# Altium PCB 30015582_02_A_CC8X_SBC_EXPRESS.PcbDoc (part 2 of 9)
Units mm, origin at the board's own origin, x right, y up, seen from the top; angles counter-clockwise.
Board outline 87 x 63 mm, 6 copper layers (Top Layer-L1, GND Plane-L2, Signal-L3, PWR/Signal-L4, GND Plane-L5, Bottom Layer-L6), stack 1.172 mm thick; 169 components, 171 nets, 693 pads, 391 vias.
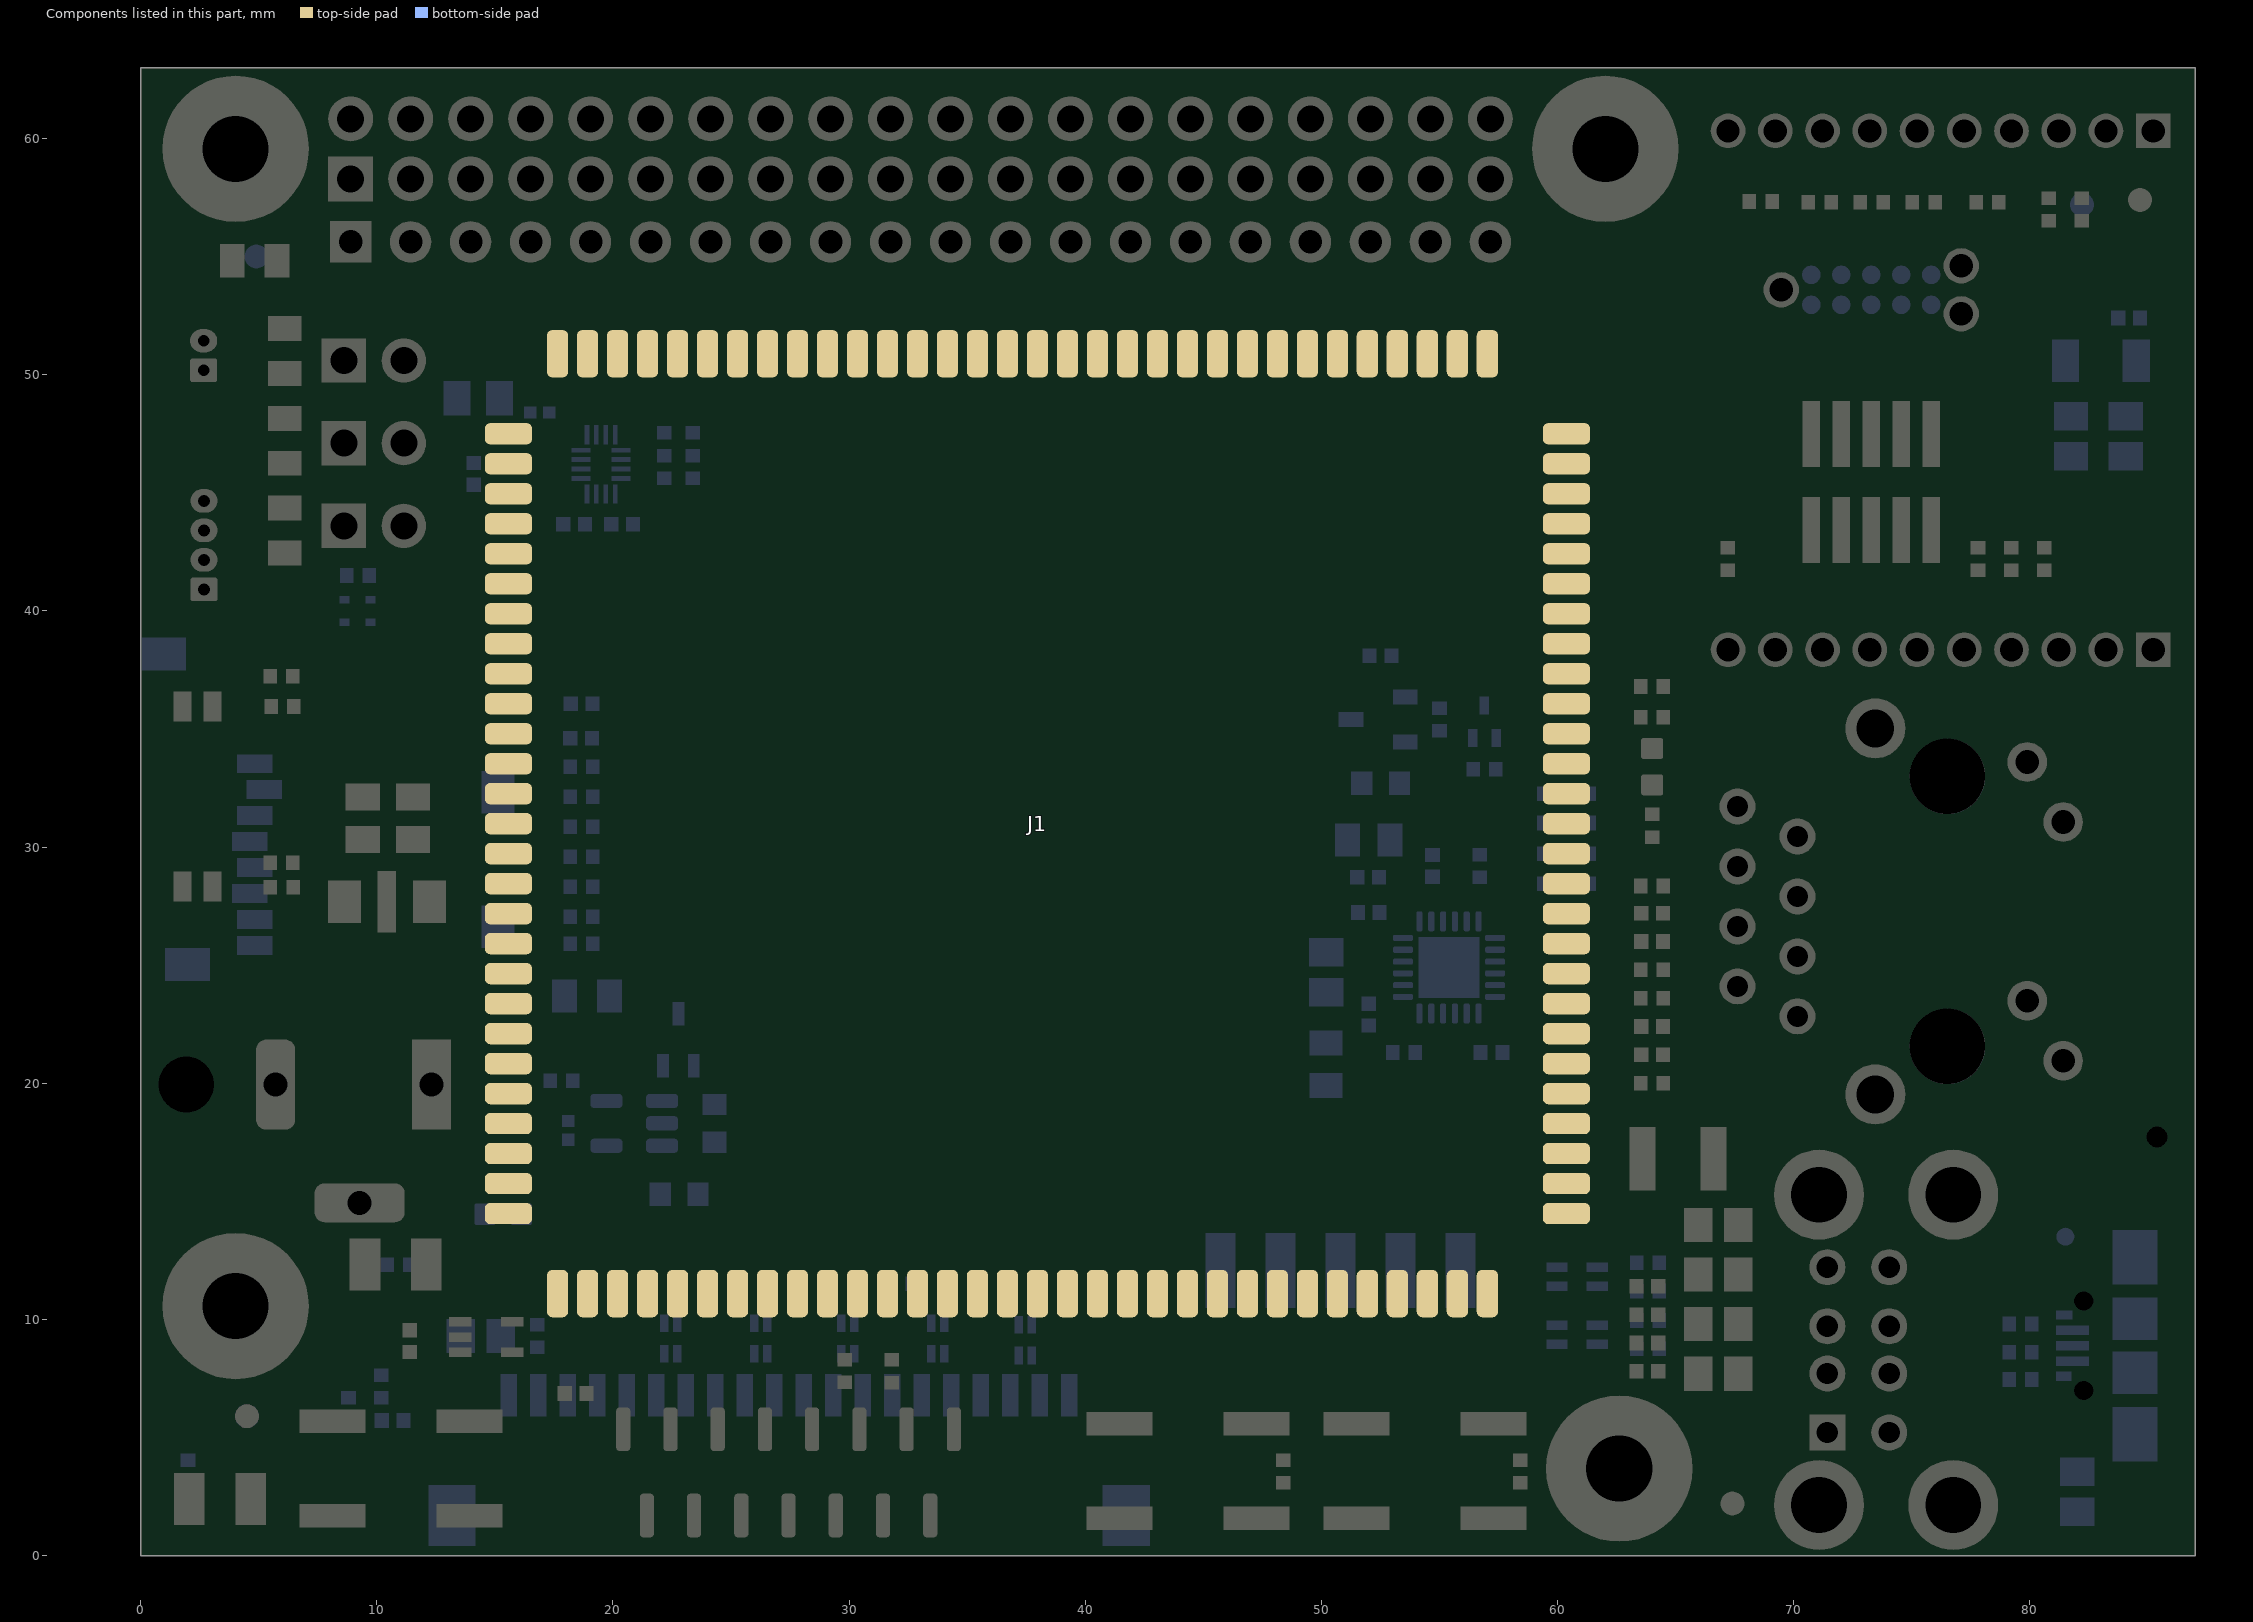
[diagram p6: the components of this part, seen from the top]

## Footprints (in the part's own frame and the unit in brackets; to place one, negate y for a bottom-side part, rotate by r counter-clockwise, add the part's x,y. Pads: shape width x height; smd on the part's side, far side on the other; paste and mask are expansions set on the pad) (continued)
CC8X_CASTELLATED [mm]
  rrect50% 2x0.9 smd: 1(-19.9,19.05) 2(-19.9,17.78) 3(-19.9,16.51) 4(-19.9,15.24) 5(-19.9,13.97) 6(-19.9,12.7) 7(-19.9,11.43) 8(-19.9,10.16) 9(-19.9,8.89) 10(-19.9,7.62) 11(-19.9,6.35) 12(-19.9,5.08) 13(-19.9,3.81) 14(-19.9,2.54) 15(-19.9,1.27) 16(-19.9,0) 17(-19.9,-1.27) 18(-19.9,-2.54) 19(-19.9,-3.81) 20(-19.9,-5.08) 21(-19.9,-6.35) 22(-19.9,-7.62) 23(-19.9,-8.89) 24(-19.9,-10.16) 25(-19.9,-11.43) 26(-19.9,-12.7) 27(-19.9,-13.97) 28(-19.9,-15.24) 29(-19.9,-16.51) 30(-19.9,-17.78) 31(-19.9,-19.05) 32(-19.9,-20.32) 60(19.9,-20.32) 61(19.9,-19.05) 62(19.9,-17.78) 63(19.9,-16.51) 64(19.9,-15.24) 65(19.9,-13.97) 66(19.9,-12.7) 67(19.9,-11.43) 68(19.9,-10.16) 69(19.9,-8.89) 70(19.9,-7.62) 71(19.9,-6.35) 72(19.9,-5.08) 73(19.9,-3.81) 74(19.9,-2.54) 75(19.9,-1.27) 76(19.9,0) 77(19.9,1.27) 78(19.9,2.54) 79(19.9,3.81) 80(19.9,5.08) 81(19.9,6.35) 82(19.9,7.62) 83(19.9,8.89) 84(19.9,10.16) 85(19.9,11.43) 86(19.9,12.7) 87(19.9,13.97) 88(19.9,15.24) 89(19.9,16.51) 90(19.9,17.78) 91(19.9,19.05)
  rrect50% 0.9x2 smd: 33(-16.51,-22.4) 34(-15.24,-22.4) 35(-13.97,-22.4) 36(-12.7,-22.4) 37(-11.43,-22.4) 38(-10.16,-22.4) 39(-8.89,-22.4) 40(-7.62,-22.4) 41(-6.35,-22.4) 42(-5.08,-22.4) 43(-3.81,-22.4) 44(-2.54,-22.4) 45(-1.27,-22.4) 46(0,-22.4) 47(1.27,-22.4) 48(2.54,-22.4) 49(3.81,-22.4) 50(5.08,-22.4) 51(6.35,-22.4) 52(7.62,-22.4) 53(8.89,-22.4) 54(10.16,-22.4) 55(11.43,-22.4) 56(12.7,-22.4) 57(13.97,-22.4) 58(15.24,-22.4) 59(16.51,-22.4) 92(16.51,22.4) 93(15.24,22.4) 94(13.97,22.4) 95(12.7,22.4) 96(11.43,22.4) 97(10.16,22.4) 98(8.89,22.4) 99(7.62,22.4) 100(6.35,22.4) 101(5.08,22.4) 102(3.81,22.4) 103(2.54,22.4) 104(1.27,22.4) 105(0,22.4) 106(-1.27,22.4) 107(-2.54,22.4) 108(-3.81,22.4) 109(-5.08,22.4) 110(-6.35,22.4) 111(-7.62,22.4) 112(-8.89,22.4) 113(-10.16,22.4) 114(-11.43,22.4) 115(-12.7,22.4) 116(-13.97,22.4) 117(-15.24,22.4) 118(-16.51,22.4)
  Top Layer-L1 keep-out region: -17.58,-10.16 -17.595,-10.237 -17.639,-10.301 -17.703,-10.345 -17.78,-10.36 -17.78,-10.36 -17.857,-10.345 -17.921,-10.301 -17.965,-10.237 -17.98,-10.16 -17.98,-10.16 -17.965,-10.083 -17.921,-10.019 -17.857,-9.975 -17.78,-9.96 -17.78,-9.96 -17.703,-9.975 -17.639,-10.019 -17.595,-10.083 -17.58,-10.16
  Top Layer-L1 keep-out region: -17.58,-8.89 -17.595,-8.967 -17.639,-9.031 -17.703,-9.075 -17.78,-9.09 -17.78,-9.09 -17.857,-9.075 -17.921,-9.031 -17.965,-8.967 -17.98,-8.89 -17.98,-8.89 -17.965,-8.813 -17.921,-8.749 -17.857,-8.705 -17.78,-8.69 -17.78,-8.69 -17.703,-8.705 -17.639,-8.749 -17.595,-8.813 -17.58,-8.89
  Top Layer-L1 keep-out region: -17.58,-7.62 -17.595,-7.697 -17.639,-7.761 -17.703,-7.805 -17.78,-7.82 -17.78,-7.82 -17.857,-7.805 -17.921,-7.761 -17.965,-7.697 -17.98,-7.62 -17.98,-7.62 -17.965,-7.543 -17.921,-7.479 -17.857,-7.435 -17.78,-7.42 -17.78,-7.42 -17.703,-7.435 -17.639,-7.479 -17.595,-7.543 -17.58,-7.62
  Top Layer-L1 keep-out region: -17.58,-6.35 -17.595,-6.427 -17.639,-6.491 -17.703,-6.535 -17.78,-6.55 -17.78,-6.55 -17.857,-6.535 -17.921,-6.491 -17.965,-6.427 -17.98,-6.35 -17.98,-6.35 -17.965,-6.273 -17.921,-6.209 -17.857,-6.165 -17.78,-6.15 -17.78,-6.15 -17.703,-6.165 -17.639,-6.209 -17.595,-6.273 -17.58,-6.35
  Top Layer-L1 keep-out region: -17.58,-5.08 -17.595,-5.157 -17.639,-5.221 -17.703,-5.265 -17.78,-5.28 -17.78,-5.28 -17.857,-5.265 -17.921,-5.221 -17.965,-5.157 -17.98,-5.08 -17.98,-5.08 -17.965,-5.003 -17.921,-4.939 -17.857,-4.895 -17.78,-4.88 -17.78,-4.88 -17.703,-4.895 -17.639,-4.939 -17.595,-5.003 -17.58,-5.08
  Top Layer-L1 keep-out region: -17.58,-3.81 -17.595,-3.887 -17.639,-3.951 -17.703,-3.995 -17.78,-4.01 -17.78,-4.01 -17.857,-3.995 -17.921,-3.951 -17.965,-3.887 -17.98,-3.81 -17.98,-3.81 -17.965,-3.733 -17.921,-3.669 -17.857,-3.625 -17.78,-3.61 -17.78,-3.61 -17.703,-3.625 -17.639,-3.669 -17.595,-3.733 -17.58,-3.81
  Top Layer-L1 keep-out region: -17.58,-2.54 -17.595,-2.617 -17.639,-2.681 -17.703,-2.725 -17.78,-2.74 -17.78,-2.74 -17.857,-2.725 -17.921,-2.681 -17.965,-2.617 -17.98,-2.54 -17.98,-2.54 -17.965,-2.463 -17.921,-2.399 -17.857,-2.355 -17.78,-2.34 -17.78,-2.34 -17.703,-2.355 -17.639,-2.399 -17.595,-2.463 -17.58,-2.54
  Top Layer-L1 keep-out region: -17.58,-1.27 -17.595,-1.347 -17.639,-1.411 -17.703,-1.455 -17.78,-1.47 -17.78,-1.47 -17.857,-1.455 -17.921,-1.411 -17.965,-1.347 -17.98,-1.27 -17.98,-1.27 -17.965,-1.193 -17.921,-1.129 -17.857,-1.085 -17.78,-1.07 -17.78,-1.07 -17.703,-1.085 -17.639,-1.129 -17.595,-1.193 -17.58,-1.27
  Top Layer-L1 keep-out region: -17.58,0 -17.595,-0.077 -17.639,-0.141 -17.703,-0.185 -17.78,-0.2 -17.78,-0.2 -17.857,-0.185 -17.921,-0.141 -17.965,-0.077 -17.98,0 -17.98,0 -17.965,0.077 -17.921,0.141 -17.857,0.185 -17.78,0.2 -17.78,0.2 -17.703,0.185 -17.639,0.141 -17.595,0.077 -17.58,0
  Top Layer-L1 keep-out region: -17.58,1.27 -17.595,1.193 -17.639,1.129 -17.703,1.085 -17.78,1.07 -17.78,1.07 -17.857,1.085 -17.921,1.129 -17.965,1.193 -17.98,1.27 -17.98,1.27 -17.965,1.347 -17.921,1.411 -17.857,1.455 -17.78,1.47 -17.78,1.47 -17.703,1.455 -17.639,1.411 -17.595,1.347 -17.58,1.27
  Top Layer-L1 keep-out region: -17.58,2.54 -17.595,2.463 -17.639,2.399 -17.703,2.355 -17.78,2.34 -17.78,2.34 -17.857,2.355 -17.921,2.399 -17.965,2.463 -17.98,2.54 -17.98,2.54 -17.965,2.617 -17.921,2.681 -17.857,2.725 -17.78,2.74 -17.78,2.74 -17.703,2.725 -17.639,2.681 -17.595,2.617 -17.58,2.54
  Top Layer-L1 keep-out region: -17.58,3.81 -17.595,3.733 -17.639,3.669 -17.703,3.625 -17.78,3.61 -17.78,3.61 -17.857,3.625 -17.921,3.669 -17.965,3.733 -17.98,3.81 -17.98,3.81 -17.965,3.887 -17.921,3.951 -17.857,3.995 -17.78,4.01 -17.78,4.01 -17.703,3.995 -17.639,3.951 -17.595,3.887 -17.58,3.81
  Top Layer-L1 keep-out region: -17.58,5.08 -17.595,5.003 -17.639,4.939 -17.703,4.895 -17.78,4.88 -17.78,4.88 -17.857,4.895 -17.921,4.939 -17.965,5.003 -17.98,5.08 -17.98,5.08 -17.965,5.157 -17.921,5.221 -17.857,5.265 -17.78,5.28 -17.78,5.28 -17.703,5.265 -17.639,5.221 -17.595,5.157 -17.58,5.08
  Top Layer-L1 keep-out region: -17.58,6.35 -17.595,6.273 -17.639,6.209 -17.703,6.165 -17.78,6.15 -17.78,6.15 -17.857,6.165 -17.921,6.209 -17.965,6.273 -17.98,6.35 -17.98,6.35 -17.965,6.427 -17.921,6.491 -17.857,6.535 -17.78,6.55 -17.78,6.55 -17.703,6.535 -17.639,6.491 -17.595,6.427 -17.58,6.35
  Top Layer-L1 keep-out region: -17.58,7.62 -17.595,7.543 -17.639,7.479 -17.703,7.435 -17.78,7.42 -17.78,7.42 -17.857,7.435 -17.921,7.479 -17.965,7.543 -17.98,7.62 -17.98,7.62 -17.965,7.697 -17.921,7.761 -17.857,7.805 -17.78,7.82 -17.78,7.82 -17.703,7.805 -17.639,7.761 -17.595,7.697 -17.58,7.62
  Top Layer-L1 keep-out region: -17.58,8.89 -17.595,8.813 -17.639,8.749 -17.703,8.705 -17.78,8.69 -17.78,8.69 -17.857,8.705 -17.921,8.749 -17.965,8.813 -17.98,8.89 -17.98,8.89 -17.965,8.967 -17.921,9.031 -17.857,9.075 -17.78,9.09 -17.78,9.09 -17.703,9.075 -17.639,9.031 -17.595,8.967 -17.58,8.89
  Top Layer-L1 keep-out region: -17.58,10.16 -17.595,10.083 -17.639,10.019 -17.703,9.975 -17.78,9.96 -17.78,9.96 -17.857,9.975 -17.921,10.019 -17.965,10.083 -17.98,10.16 -17.98,10.16 -17.965,10.237 -17.921,10.301 -17.857,10.345 -17.78,10.36 -17.78,10.36 -17.703,10.345 -17.639,10.301 -17.595,10.237 -17.58,10.16
  Top Layer-L1 keep-out region: 17.98,-10.16 17.965,-10.237 17.921,-10.301 17.857,-10.345 17.78,-10.36 17.78,-10.36 17.703,-10.345 17.639,-10.301 17.595,-10.237 17.58,-10.16 17.58,-10.16 17.595,-10.083 17.639,-10.019 17.703,-9.975 17.78,-9.96 17.78,-9.96 17.857,-9.975 17.921,-10.019 17.965,-10.083 17.98,-10.16
  Top Layer-L1 keep-out region: 17.98,-8.89 17.965,-8.967 17.921,-9.031 17.857,-9.075 17.78,-9.09 17.78,-9.09 17.703,-9.075 17.639,-9.031 17.595,-8.967 17.58,-8.89 17.58,-8.89 17.595,-8.813 17.639,-8.749 17.703,-8.705 17.78,-8.69 17.78,-8.69 17.857,-8.705 17.921,-8.749 17.965,-8.813 17.98,-8.89
  Top Layer-L1 keep-out region: 17.98,-7.62 17.965,-7.697 17.921,-7.761 17.857,-7.805 17.78,-7.82 17.78,-7.82 17.703,-7.805 17.639,-7.761 17.595,-7.697 17.58,-7.62 17.58,-7.62 17.595,-7.543 17.639,-7.479 17.703,-7.435 17.78,-7.42 17.78,-7.42 17.857,-7.435 17.921,-7.479 17.965,-7.543 17.98,-7.62
  Top Layer-L1 keep-out region: 17.98,-6.35 17.965,-6.427 17.921,-6.491 17.857,-6.535 17.78,-6.55 17.78,-6.55 17.703,-6.535 17.639,-6.491 17.595,-6.427 17.58,-6.35 17.58,-6.35 17.595,-6.273 17.639,-6.209 17.703,-6.165 17.78,-6.15 17.78,-6.15 17.857,-6.165 17.921,-6.209 17.965,-6.273 17.98,-6.35
  Top Layer-L1 keep-out region: 17.98,-5.08 17.965,-5.157 17.921,-5.221 17.857,-5.265 17.78,-5.28 17.78,-5.28 17.703,-5.265 17.639,-5.221 17.595,-5.157 17.58,-5.08 17.58,-5.08 17.595,-5.003 17.639,-4.939 17.703,-4.895 17.78,-4.88 17.78,-4.88 17.857,-4.895 17.921,-4.939 17.965,-5.003 17.98,-5.08
  Top Layer-L1 keep-out region: 17.98,-3.81 17.965,-3.887 17.921,-3.951 17.857,-3.995 17.78,-4.01 17.78,-4.01 17.703,-3.995 17.639,-3.951 17.595,-3.887 17.58,-3.81 17.58,-3.81 17.595,-3.733 17.639,-3.669 17.703,-3.625 17.78,-3.61 17.78,-3.61 17.857,-3.625 17.921,-3.669 17.965,-3.733 17.98,-3.81
  Top Layer-L1 keep-out region: 17.98,-2.54 17.965,-2.617 17.921,-2.681 17.857,-2.725 17.78,-2.74 17.78,-2.74 17.703,-2.725 17.639,-2.681 17.595,-2.617 17.58,-2.54 17.58,-2.54 17.595,-2.463 17.639,-2.399 17.703,-2.355 17.78,-2.34 17.78,-2.34 17.857,-2.355 17.921,-2.399 17.965,-2.463 17.98,-2.54
  Top Layer-L1 keep-out region: 17.98,-1.27 17.965,-1.347 17.921,-1.411 17.857,-1.455 17.78,-1.47 17.78,-1.47 17.703,-1.455 17.639,-1.411 17.595,-1.347 17.58,-1.27 17.58,-1.27 17.595,-1.193 17.639,-1.129 17.703,-1.085 17.78,-1.07 17.78,-1.07 17.857,-1.085 17.921,-1.129 17.965,-1.193 17.98,-1.27
  Top Layer-L1 keep-out region: 17.98,0 17.965,-0.077 17.921,-0.141 17.857,-0.185 17.78,-0.2 17.78,-0.2 17.703,-0.185 17.639,-0.141 17.595,-0.077 17.58,0 17.58,0 17.595,0.077 17.639,0.141 17.703,0.185 17.78,0.2 17.78,0.2 17.857,0.185 17.921,0.141 17.965,0.077 17.98,0
  Top Layer-L1 keep-out region: 17.98,1.27 17.965,1.193 17.921,1.129 17.857,1.085 17.78,1.07 17.78,1.07 17.703,1.085 17.639,1.129 17.595,1.193 17.58,1.27 17.58,1.27 17.595,1.347 17.639,1.411 17.703,1.455 17.78,1.47 17.78,1.47 17.857,1.455 17.921,1.411 17.965,1.347 17.98,1.27
  Top Layer-L1 keep-out region: 17.98,2.54 17.965,2.463 17.921,2.399 17.857,2.355 17.78,2.34 17.78,2.34 17.703,2.355 17.639,2.399 17.595,2.463 17.58,2.54 17.58,2.54 17.595,2.617 17.639,2.681 17.703,2.725 17.78,2.74 17.78,2.74 17.857,2.725 17.921,2.681 17.965,2.617 17.98,2.54
  Top Layer-L1 keep-out region: 17.98,3.81 17.965,3.733 17.921,3.669 17.857,3.625 17.78,3.61 17.78,3.61 17.703,3.625 17.639,3.669 17.595,3.733 17.58,3.81 17.58,3.81 17.595,3.887 17.639,3.951 17.703,3.995 17.78,4.01 17.78,4.01 17.857,3.995 17.921,3.951 17.965,3.887 17.98,3.81
  Top Layer-L1 keep-out region: 17.98,5.08 17.965,5.003 17.921,4.939 17.857,4.895 17.78,4.88 17.78,4.88 17.703,4.895 17.639,4.939 17.595,5.003 17.58,5.08 17.58,5.08 17.595,5.157 17.639,5.221 17.703,5.265 17.78,5.28 17.78,5.28 17.857,5.265 17.921,5.221 17.965,5.157 17.98,5.08
  Top Layer-L1 keep-out region: 17.98,6.35 17.965,6.273 17.921,6.209 17.857,6.165 17.78,6.15 17.78,6.15 17.703,6.165 17.639,6.209 17.595,6.273 17.58,6.35 17.58,6.35 17.595,6.427 17.639,6.491 17.703,6.535 17.78,6.55 17.78,6.55 17.857,6.535 17.921,6.491 17.965,6.427 17.98,6.35
  Top Layer-L1 keep-out region: 17.98,7.62 17.965,7.543 17.921,7.479 17.857,7.435 17.78,7.42 17.78,7.42 17.703,7.435 17.639,7.479 17.595,7.543 17.58,7.62 17.58,7.62 17.595,7.697 17.639,7.761 17.703,7.805 17.78,7.82 17.78,7.82 17.857,7.805 17.921,7.761 17.965,7.697 17.98,7.62
  Top Layer-L1 keep-out region: 17.98,8.89 17.965,8.813 17.921,8.749 17.857,8.705 17.78,8.69 17.78,8.69 17.703,8.705 17.639,8.749 17.595,8.813 17.58,8.89 17.58,8.89 17.595,8.967 17.639,9.031 17.703,9.075 17.78,9.09 17.78,9.09 17.857,9.075 17.921,9.031 17.965,8.967 17.98,8.89
  Top Layer-L1 keep-out region: 17.98,10.16 17.965,10.083 17.921,10.019 17.857,9.975 17.78,9.96 17.78,9.96 17.703,9.975 17.639,10.019 17.595,10.083 17.58,10.16 17.58,10.16 17.595,10.237 17.639,10.301 17.703,10.345 17.78,10.36 17.78,10.36 17.857,10.345 17.921,10.301 17.965,10.237 17.98,10.16
  Top Layer-L1 keep-out region: 14.17,-20.32 14.155,-20.397 14.111,-20.461 14.047,-20.505 13.97,-20.52 13.97,-20.52 13.893,-20.505 13.829,-20.461 13.785,-20.397 13.77,-20.32 13.77,-20.32 13.785,-20.243 13.829,-20.179 13.893,-20.135 13.97,-20.12 13.97,-20.12 14.047,-20.135 14.111,-20.179 14.155,-20.243 14.17,-20.32
  Top Layer-L1 keep-out region: 12.9,-20.32 12.885,-20.397 12.841,-20.461 12.777,-20.505 12.7,-20.52 12.7,-20.52 12.623,-20.505 12.559,-20.461 12.515,-20.397 12.5,-20.32 12.5,-20.32 12.515,-20.243 12.559,-20.179 12.623,-20.135 12.7,-20.12 12.7,-20.12 12.777,-20.135 12.841,-20.179 12.885,-20.243 12.9,-20.32
  Top Layer-L1 keep-out region: 11.63,-20.32 11.615,-20.397 11.571,-20.461 11.507,-20.505 11.43,-20.52 11.43,-20.52 11.353,-20.505 11.289,-20.461 11.245,-20.397 11.23,-20.32 11.23,-20.32 11.245,-20.243 11.289,-20.179 11.353,-20.135 11.43,-20.12 11.43,-20.12 11.507,-20.135 11.571,-20.179 11.615,-20.243 11.63,-20.32
  Top Layer-L1 keep-out region: 10.36,-20.32 10.345,-20.397 10.301,-20.461 10.237,-20.505 10.16,-20.52 10.16,-20.52 10.083,-20.505 10.019,-20.461 9.975,-20.397 9.96,-20.32 9.96,-20.32 9.975,-20.243 10.019,-20.179 10.083,-20.135 10.16,-20.12 10.16,-20.12 10.237,-20.135 10.301,-20.179 10.345,-20.243 10.36,-20.32
  Top Layer-L1 keep-out region: 9.09,-20.32 9.075,-20.397 9.031,-20.461 8.967,-20.505 8.89,-20.52 8.89,-20.52 8.813,-20.505 8.749,-20.461 8.705,-20.397 8.69,-20.32 8.69,-20.32 8.705,-20.243 8.749,-20.179 8.813,-20.135 8.89,-20.12 8.89,-20.12 8.967,-20.135 9.031,-20.179 9.075,-20.243 9.09,-20.32
  Top Layer-L1 keep-out region: 7.82,-20.32 7.805,-20.397 7.761,-20.461 7.697,-20.505 7.62,-20.52 7.62,-20.52 7.543,-20.505 7.479,-20.461 7.435,-20.397 7.42,-20.32 7.42,-20.32 7.435,-20.243 7.479,-20.179 7.543,-20.135 7.62,-20.12 7.62,-20.12 7.697,-20.135 7.761,-20.179 7.805,-20.243 7.82,-20.32
  Top Layer-L1 keep-out region: 6.55,-20.32 6.535,-20.397 6.491,-20.461 6.427,-20.505 6.35,-20.52 6.35,-20.52 6.273,-20.505 6.209,-20.461 6.165,-20.397 6.15,-20.32 6.15,-20.32 6.165,-20.243 6.209,-20.179 6.273,-20.135 6.35,-20.12 6.35,-20.12 6.427,-20.135 6.491,-20.179 6.535,-20.243 6.55,-20.32
  Top Layer-L1 keep-out region: 5.28,-20.32 5.265,-20.397 5.221,-20.461 5.157,-20.505 5.08,-20.52 5.08,-20.52 5.003,-20.505 4.939,-20.461 4.895,-20.397 4.88,-20.32 4.88,-20.32 4.895,-20.243 4.939,-20.179 5.003,-20.135 5.08,-20.12 5.08,-20.12 5.157,-20.135 5.221,-20.179 5.265,-20.243 5.28,-20.32
  Top Layer-L1 keep-out region: 4.01,-20.32 3.995,-20.397 3.951,-20.461 3.887,-20.505 3.81,-20.52 3.81,-20.52 3.733,-20.505 3.669,-20.461 3.625,-20.397 3.61,-20.32 3.61,-20.32 3.625,-20.243 3.669,-20.179 3.733,-20.135 3.81,-20.12 3.81,-20.12 3.887,-20.135 3.951,-20.179 3.995,-20.243 4.01,-20.32
  Top Layer-L1 keep-out region: 2.74,-20.32 2.725,-20.397 2.681,-20.461 2.617,-20.505 2.54,-20.52 2.54,-20.52 2.463,-20.505 2.399,-20.461 2.355,-20.397 2.34,-20.32 2.34,-20.32 2.355,-20.243 2.399,-20.179 2.463,-20.135 2.54,-20.12 2.54,-20.12 2.617,-20.135 2.681,-20.179 2.725,-20.243 2.74,-20.32
  Top Layer-L1 keep-out region: 1.47,-20.32 1.455,-20.397 1.411,-20.461 1.347,-20.505 1.27,-20.52 1.27,-20.52 1.193,-20.505 1.129,-20.461 1.085,-20.397 1.07,-20.32 1.07,-20.32 1.085,-20.243 1.129,-20.179 1.193,-20.135 1.27,-20.12 1.27,-20.12 1.347,-20.135 1.411,-20.179 1.455,-20.243 1.47,-20.32
  Top Layer-L1 keep-out region: 0.2,-20.32 0.185,-20.397 0.141,-20.461 0.077,-20.505 0,-20.52 0,-20.52 -0.077,-20.505 -0.141,-20.461 -0.185,-20.397 -0.2,-20.32 -0.2,-20.32 -0.185,-20.243 -0.141,-20.179 -0.077,-20.135 0,-20.12 0,-20.12 0.077,-20.135 0.141,-20.179 0.185,-20.243 0.2,-20.32
  Top Layer-L1 keep-out region: -1.07,-20.32 -1.085,-20.397 -1.129,-20.461 -1.193,-20.505 -1.27,-20.52 -1.27,-20.52 -1.347,-20.505 -1.411,-20.461 -1.455,-20.397 -1.47,-20.32 -1.47,-20.32 -1.455,-20.243 -1.411,-20.179 -1.347,-20.135 -1.27,-20.12 -1.27,-20.12 -1.193,-20.135 -1.129,-20.179 -1.085,-20.243 -1.07,-20.32
  Top Layer-L1 keep-out region: -2.34,-20.32 -2.355,-20.397 -2.399,-20.461 -2.463,-20.505 -2.54,-20.52 -2.54,-20.52 -2.617,-20.505 -2.681,-20.461 -2.725,-20.397 -2.74,-20.32 -2.74,-20.32 -2.725,-20.243 -2.681,-20.179 -2.617,-20.135 -2.54,-20.12 -2.54,-20.12 -2.463,-20.135 -2.399,-20.179 -2.355,-20.243 -2.34,-20.32
  Top Layer-L1 keep-out region: -3.61,-20.32 -3.625,-20.397 -3.669,-20.461 -3.733,-20.505 -3.81,-20.52 -3.81,-20.52 -3.887,-20.505 -3.951,-20.461 -3.995,-20.397 -4.01,-20.32 -4.01,-20.32 -3.995,-20.243 -3.951,-20.179 -3.887,-20.135 -3.81,-20.12 -3.81,-20.12 -3.733,-20.135 -3.669,-20.179 -3.625,-20.243 -3.61,-20.32
  Top Layer-L1 keep-out region: -4.88,-20.32 -4.895,-20.397 -4.939,-20.461 -5.003,-20.505 -5.08,-20.52 -5.08,-20.52 -5.157,-20.505 -5.221,-20.461 -5.265,-20.397 -5.28,-20.32 -5.28,-20.32 -5.265,-20.243 -5.221,-20.179 -5.157,-20.135 -5.08,-20.12 -5.08,-20.12 -5.003,-20.135 -4.939,-20.179 -4.895,-20.243 -4.88,-20.32
  Top Layer-L1 keep-out region: -6.15,-20.32 -6.165,-20.397 -6.209,-20.461 -6.273,-20.505 -6.35,-20.52 -6.35,-20.52 -6.427,-20.505 -6.491,-20.461 -6.535,-20.397 -6.55,-20.32 -6.55,-20.32 -6.535,-20.243 -6.491,-20.179 -6.427,-20.135 -6.35,-20.12 -6.35,-20.12 -6.273,-20.135 -6.209,-20.179 -6.165,-20.243 -6.15,-20.32
  Top Layer-L1 keep-out region: -7.42,-20.32 -7.435,-20.397 -7.479,-20.461 -7.543,-20.505 -7.62,-20.52 -7.62,-20.52 -7.697,-20.505 -7.761,-20.461 -7.805,-20.397 -7.82,-20.32 -7.82,-20.32 -7.805,-20.243 -7.761,-20.179 -7.697,-20.135 -7.62,-20.12 -7.62,-20.12 -7.543,-20.135 -7.479,-20.179 -7.435,-20.243 -7.42,-20.32
  Top Layer-L1 keep-out region: -8.69,-20.32 -8.705,-20.397 -8.749,-20.461 -8.813,-20.505 -8.89,-20.52 -8.89,-20.52 -8.967,-20.505 -9.031,-20.461 -9.075,-20.397 -9.09,-20.32 -9.09,-20.32 -9.075,-20.243 -9.031,-20.179 -8.967,-20.135 -8.89,-20.12 -8.89,-20.12 -8.813,-20.135 -8.749,-20.179 -8.705,-20.243 -8.69,-20.32
  Top Layer-L1 keep-out region: -9.96,-20.32 -9.975,-20.397 -10.019,-20.461 -10.083,-20.505 -10.16,-20.52 -10.16,-20.52 -10.237,-20.505 -10.301,-20.461 -10.345,-20.397 -10.36,-20.32 -10.36,-20.32 -10.345,-20.243 -10.301,-20.179 -10.237,-20.135 -10.16,-20.12 -10.16,-20.12 -10.083,-20.135 -10.019,-20.179 -9.975,-20.243 -9.96,-20.32
  Top Layer-L1 keep-out region: -11.23,-20.32 -11.245,-20.397 -11.289,-20.461 -11.353,-20.505 -11.43,-20.52 -11.43,-20.52 -11.507,-20.505 -11.571,-20.461 -11.615,-20.397 -11.63,-20.32 -11.63,-20.32 -11.615,-20.243 -11.571,-20.179 -11.507,-20.135 -11.43,-20.12 -11.43,-20.12 -11.353,-20.135 -11.289,-20.179 -11.245,-20.243 -11.23,-20.32
  Top Layer-L1 keep-out region: -12.5,-20.32 -12.515,-20.397 -12.559,-20.461 -12.623,-20.505 -12.7,-20.52 -12.7,-20.52 -12.777,-20.505 -12.841,-20.461 -12.885,-20.397 -12.9,-20.32 -12.9,-20.32 -12.885,-20.243 -12.841,-20.179 -12.777,-20.135 -12.7,-20.12 -12.7,-20.12 -12.623,-20.135 -12.559,-20.179 -12.515,-20.243 -12.5,-20.32
  Top Layer-L1 keep-out region: -13.77,-20.32 -13.785,-20.397 -13.829,-20.461 -13.893,-20.505 -13.97,-20.52 -13.97,-20.52 -14.047,-20.505 -14.111,-20.461 -14.155,-20.397 -14.17,-20.32 -14.17,-20.32 -14.155,-20.243 -14.111,-20.179 -14.047,-20.135 -13.97,-20.12 -13.97,-20.12 -13.893,-20.135 -13.829,-20.179 -13.785,-20.243 -13.77,-20.32
  Top Layer-L1 keep-out region: 15.44,-19.05 15.425,-19.127 15.381,-19.191 15.317,-19.235 15.24,-19.25 15.24,-19.25 15.163,-19.235 15.099,-19.191 15.055,-19.127 15.04,-19.05 15.04,-19.05 15.055,-18.973 15.099,-18.909 15.163,-18.865 15.24,-18.85 15.24,-18.85 15.317,-18.865 15.381,-18.909 15.425,-18.973 15.44,-19.05
  Top Layer-L1 keep-out region: 14.17,-19.05 14.155,-19.127 14.111,-19.191 14.047,-19.235 13.97,-19.25 13.97,-19.25 13.893,-19.235 13.829,-19.191 13.785,-19.127 13.77,-19.05 13.77,-19.05 13.785,-18.973 13.829,-18.909 13.893,-18.865 13.97,-18.85 13.97,-18.85 14.047,-18.865 14.111,-18.909 14.155,-18.973 14.17,-19.05
  Top Layer-L1 keep-out region: 12.9,-19.05 12.885,-19.127 12.841,-19.191 12.777,-19.235 12.7,-19.25 12.7,-19.25 12.623,-19.235 12.559,-19.191 12.515,-19.127 12.5,-19.05 12.5,-19.05 12.515,-18.973 12.559,-18.909 12.623,-18.865 12.7,-18.85 12.7,-18.85 12.777,-18.865 12.841,-18.909 12.885,-18.973 12.9,-19.05
  Top Layer-L1 keep-out region: 11.63,-19.05 11.615,-19.127 11.571,-19.191 11.507,-19.235 11.43,-19.25 11.43,-19.25 11.353,-19.235 11.289,-19.191 11.245,-19.127 11.23,-19.05 11.23,-19.05 11.245,-18.973 11.289,-18.909 11.353,-18.865 11.43,-18.85 11.43,-18.85 11.507,-18.865 11.571,-18.909 11.615,-18.973 11.63,-19.05
  Top Layer-L1 keep-out region: 10.36,-19.05 10.345,-19.127 10.301,-19.191 10.237,-19.235 10.16,-19.25 10.16,-19.25 10.083,-19.235 10.019,-19.191 9.975,-19.127 9.96,-19.05 9.96,-19.05 9.975,-18.973 10.019,-18.909 10.083,-18.865 10.16,-18.85 10.16,-18.85 10.237,-18.865 10.301,-18.909 10.345,-18.973 10.36,-19.05
  Top Layer-L1 keep-out region: 9.09,-19.05 9.075,-19.127 9.031,-19.191 8.967,-19.235 8.89,-19.25 8.89,-19.25 8.813,-19.235 8.749,-19.191 8.705,-19.127 8.69,-19.05 8.69,-19.05 8.705,-18.973 8.749,-18.909 8.813,-18.865 8.89,-18.85 8.89,-18.85 8.967,-18.865 9.031,-18.909 9.075,-18.973 9.09,-19.05
  Top Layer-L1 keep-out region: 7.82,-19.05 7.805,-19.127 7.761,-19.191 7.697,-19.235 7.62,-19.25 7.62,-19.25 7.543,-19.235 7.479,-19.191 7.435,-19.127 7.42,-19.05 7.42,-19.05 7.435,-18.973 7.479,-18.909 7.543,-18.865 7.62,-18.85 7.62,-18.85 7.697,-18.865 7.761,-18.909 7.805,-18.973 7.82,-19.05
  Top Layer-L1 keep-out region: 6.55,-19.05 6.535,-19.127 6.491,-19.191 6.427,-19.235 6.35,-19.25 6.35,-19.25 6.273,-19.235 6.209,-19.191 6.165,-19.127 6.15,-19.05 6.15,-19.05 6.165,-18.973 6.209,-18.909 6.273,-18.865 6.35,-18.85 6.35,-18.85 6.427,-18.865 6.491,-18.909 6.535,-18.973 6.55,-19.05
  Top Layer-L1 keep-out region: 5.28,-19.05 5.265,-19.127 5.221,-19.191 5.157,-19.235 5.08,-19.25 5.08,-19.25 5.003,-19.235 4.939,-19.191 4.895,-19.127 4.88,-19.05 4.88,-19.05 4.895,-18.973 4.939,-18.909 5.003,-18.865 5.08,-18.85 5.08,-18.85 5.157,-18.865 5.221,-18.909 5.265,-18.973 5.28,-19.05
  Top Layer-L1 keep-out region: 4.01,-19.05 3.995,-19.127 3.951,-19.191 3.887,-19.235 3.81,-19.25 3.81,-19.25 3.733,-19.235 3.669,-19.191 3.625,-19.127 3.61,-19.05 3.61,-19.05 3.625,-18.973 3.669,-18.909 3.733,-18.865 3.81,-18.85 3.81,-18.85 3.887,-18.865 3.951,-18.909 3.995,-18.973 4.01,-19.05
  Top Layer-L1 keep-out region: 2.74,-19.05 2.725,-19.127 2.681,-19.191 2.617,-19.235 2.54,-19.25 2.54,-19.25 2.463,-19.235 2.399,-19.191 2.355,-19.127 2.34,-19.05 2.34,-19.05 2.355,-18.973 2.399,-18.909 2.463,-18.865 2.54,-18.85 2.54,-18.85 2.617,-18.865 2.681,-18.909 2.725,-18.973 2.74,-19.05
  Top Layer-L1 keep-out region: 1.47,-19.05 1.455,-19.127 1.411,-19.191 1.347,-19.235 1.27,-19.25 1.27,-19.25 1.193,-19.235 1.129,-19.191 1.085,-19.127 1.07,-19.05 1.07,-19.05 1.085,-18.973 1.129,-18.909 1.193,-18.865 1.27,-18.85 1.27,-18.85 1.347,-18.865 1.411,-18.909 1.455,-18.973 1.47,-19.05
  Top Layer-L1 keep-out region: 0.2,-19.05 0.185,-19.127 0.141,-19.191 0.077,-19.235 0,-19.25 0,-19.25 -0.077,-19.235 -0.141,-19.191 -0.185,-19.127 -0.2,-19.05 -0.2,-19.05 -0.185,-18.973 -0.141,-18.909 -0.077,-18.865 0,-18.85 0,-18.85 0.077,-18.865 0.141,-18.909 0.185,-18.973 0.2,-19.05
  Top Layer-L1 keep-out region: -1.07,-19.05 -1.085,-19.127 -1.129,-19.191 -1.193,-19.235 -1.27,-19.25 -1.27,-19.25 -1.347,-19.235 -1.411,-19.191 -1.455,-19.127 -1.47,-19.05 -1.47,-19.05 -1.455,-18.973 -1.411,-18.909 -1.347,-18.865 -1.27,-18.85 -1.27,-18.85 -1.193,-18.865 -1.129,-18.909 -1.085,-18.973 -1.07,-19.05
  Top Layer-L1 keep-out region: -2.34,-19.05 -2.355,-19.127 -2.399,-19.191 -2.463,-19.235 -2.54,-19.25 -2.54,-19.25 -2.617,-19.235 -2.681,-19.191 -2.725,-19.127 -2.74,-19.05 -2.74,-19.05 -2.725,-18.973 -2.681,-18.909 -2.617,-18.865 -2.54,-18.85 -2.54,-18.85 -2.463,-18.865 -2.399,-18.909 -2.355,-18.973 -2.34,-19.05
  Top Layer-L1 keep-out region: -3.61,-19.05 -3.625,-19.127 -3.669,-19.191 -3.733,-19.235 -3.81,-19.25 -3.81,-19.25 -3.887,-19.235 -3.951,-19.191 -3.995,-19.127 -4.01,-19.05 -4.01,-19.05 -3.995,-18.973 -3.951,-18.909 -3.887,-18.865 -3.81,-18.85 -3.81,-18.85 -3.733,-18.865 -3.669,-18.909 -3.625,-18.973 -3.61,-19.05
  Top Layer-L1 keep-out region: -4.88,-19.05 -4.895,-19.127 -4.939,-19.191 -5.003,-19.235 -5.08,-19.25 -5.08,-19.25 -5.157,-19.235 -5.221,-19.191 -5.265,-19.127 -5.28,-19.05 -5.28,-19.05 -5.265,-18.973 -5.221,-18.909 -5.157,-18.865 -5.08,-18.85 -5.08,-18.85 -5.003,-18.865 -4.939,-18.909 -4.895,-18.973 -4.88,-19.05
  Top Layer-L1 keep-out region: -6.15,-19.05 -6.165,-19.127 -6.209,-19.191 -6.273,-19.235 -6.35,-19.25 -6.35,-19.25 -6.427,-19.235 -6.491,-19.191 -6.535,-19.127 -6.55,-19.05 -6.55,-19.05 -6.535,-18.973 -6.491,-18.909 -6.427,-18.865 -6.35,-18.85 -6.35,-18.85 -6.273,-18.865 -6.209,-18.909 -6.165,-18.973 -6.15,-19.05
  Top Layer-L1 keep-out region: -7.42,-19.05 -7.435,-19.127 -7.479,-19.191 -7.543,-19.235 -7.62,-19.25 -7.62,-19.25 -7.697,-19.235 -7.761,-19.191 -7.805,-19.127 -7.82,-19.05 -7.82,-19.05 -7.805,-18.973 -7.761,-18.909 -7.697,-18.865 -7.62,-18.85 -7.62,-18.85 -7.543,-18.865 -7.479,-18.909 -7.435,-18.973 -7.42,-19.05
  Top Layer-L1 keep-out region: -8.69,-19.05 -8.705,-19.127 -8.749,-19.191 -8.813,-19.235 -8.89,-19.25 -8.89,-19.25 -8.967,-19.235 -9.031,-19.191 -9.075,-19.127 -9.09,-19.05 -9.09,-19.05 -9.075,-18.973 -9.031,-18.909 -8.967,-18.865 -8.89,-18.85 -8.89,-18.85 -8.813,-18.865 -8.749,-18.909 -8.705,-18.973 -8.69,-19.05
  Top Layer-L1 keep-out region: -9.96,-19.05 -9.975,-19.127 -10.019,-19.191 -10.083,-19.235 -10.16,-19.25 -10.16,-19.25 -10.237,-19.235 -10.301,-19.191 -10.345,-19.127 -10.36,-19.05 -10.36,-19.05 -10.345,-18.973 -10.301,-18.909 -10.237,-18.865 -10.16,-18.85 -10.16,-18.85 -10.083,-18.865 -10.019,-18.909 -9.975,-18.973 -9.96,-19.05
  Top Layer-L1 keep-out region: -11.23,-19.05 -11.245,-19.127 -11.289,-19.191 -11.353,-19.235 -11.43,-19.25 -11.43,-19.25 -11.507,-19.235 -11.571,-19.191 -11.615,-19.127 -11.63,-19.05 -11.63,-19.05 -11.615,-18.973 -11.571,-18.909 -11.507,-18.865 -11.43,-18.85 -11.43,-18.85 -11.353,-18.865 -11.289,-18.909 -11.245,-18.973 -11.23,-19.05
  Top Layer-L1 keep-out region: -12.5,-19.05 -12.515,-19.127 -12.559,-19.191 -12.623,-19.235 -12.7,-19.25 -12.7,-19.25 -12.777,-19.235 -12.841,-19.191 -12.885,-19.127 -12.9,-19.05 -12.9,-19.05 -12.885,-18.973 -12.841,-18.909 -12.777,-18.865 -12.7,-18.85 -12.7,-18.85 -12.623,-18.865 -12.559,-18.909 -12.515,-18.973 -12.5,-19.05
  Top Layer-L1 keep-out region: -13.77,-19.05 -13.785,-19.127 -13.829,-19.191 -13.893,-19.235 -13.97,-19.25 -13.97,-19.25 -14.047,-19.235 -14.111,-19.191 -14.155,-19.127 -14.17,-19.05 -14.17,-19.05 -14.155,-18.973 -14.111,-18.909 -14.047,-18.865 -13.97,-18.85 -13.97,-18.85 -13.893,-18.865 -13.829,-18.909 -13.785,-18.973 -13.77,-19.05
  Top Layer-L1 keep-out region: -15.04,-19.05 -15.055,-19.127 -15.099,-19.191 -15.163,-19.235 -15.24,-19.25 -15.24,-19.25 -15.317,-19.235 -15.381,-19.191 -15.425,-19.127 -15.44,-19.05 -15.44,-19.05 -15.425,-18.973 -15.381,-18.909 -15.317,-18.865 -15.24,-18.85 -15.24,-18.85 -15.163,-18.865 -15.099,-18.909 -15.055,-18.973 -15.04,-19.05
  Top Layer-L1 keep-out region: 16.71,-17.78 16.695,-17.857 16.651,-17.921 16.587,-17.965 16.51,-17.98 16.51,-17.98 16.433,-17.965 16.369,-17.921 16.325,-17.857 16.31,-17.78 16.31,-17.78 16.325,-17.703 16.369,-17.639 16.433,-17.595 16.51,-17.58 16.51,-17.58 16.587,-17.595 16.651,-17.639 16.695,-17.703 16.71,-17.78
  Top Layer-L1 keep-out region: 15.44,-17.78 15.425,-17.857 15.381,-17.921 15.317,-17.965 15.24,-17.98 15.24,-17.98 15.163,-17.965 15.099,-17.921 15.055,-17.857 15.04,-17.78 15.04,-17.78 15.055,-17.703 15.099,-17.639 15.163,-17.595 15.24,-17.58 15.24,-17.58 15.317,-17.595 15.381,-17.639 15.425,-17.703 15.44,-17.78
  Top Layer-L1 keep-out region: 14.17,-17.78 14.155,-17.857 14.111,-17.921 14.047,-17.965 13.97,-17.98 13.97,-17.98 13.893,-17.965 13.829,-17.921 13.785,-17.857 13.77,-17.78 13.77,-17.78 13.785,-17.703 13.829,-17.639 13.893,-17.595 13.97,-17.58 13.97,-17.58 14.047,-17.595 14.111,-17.639 14.155,-17.703 14.17,-17.78
  Top Layer-L1 keep-out region: 12.9,-17.78 12.885,-17.857 12.841,-17.921 12.777,-17.965 12.7,-17.98 12.7,-17.98 12.623,-17.965 12.559,-17.921 12.515,-17.857 12.5,-17.78 12.5,-17.78 12.515,-17.703 12.559,-17.639 12.623,-17.595 12.7,-17.58 12.7,-17.58 12.777,-17.595 12.841,-17.639 12.885,-17.703 12.9,-17.78
  Top Layer-L1 keep-out region: 11.63,-17.78 11.615,-17.857 11.571,-17.921 11.507,-17.965 11.43,-17.98 11.43,-17.98 11.353,-17.965 11.289,-17.921 11.245,-17.857 11.23,-17.78 11.23,-17.78 11.245,-17.703 11.289,-17.639 11.353,-17.595 11.43,-17.58 11.43,-17.58 11.507,-17.595 11.571,-17.639 11.615,-17.703 11.63,-17.78
  Top Layer-L1 keep-out region: 10.36,-17.78 10.345,-17.857 10.301,-17.921 10.237,-17.965 10.16,-17.98 10.16,-17.98 10.083,-17.965 10.019,-17.921 9.975,-17.857 9.96,-17.78 9.96,-17.78 9.975,-17.703 10.019,-17.639 10.083,-17.595 10.16,-17.58 10.16,-17.58 10.237,-17.595 10.301,-17.639 10.345,-17.703 10.36,-17.78
  Top Layer-L1 keep-out region: 9.09,-17.78 9.075,-17.857 9.031,-17.921 8.967,-17.965 8.89,-17.98 8.89,-17.98 8.813,-17.965 8.749,-17.921 8.705,-17.857 8.69,-17.78 8.69,-17.78 8.705,-17.703 8.749,-17.639 8.813,-17.595 8.89,-17.58 8.89,-17.58 8.967,-17.595 9.031,-17.639 9.075,-17.703 9.09,-17.78
  Top Layer-L1 keep-out region: 7.82,-17.78 7.805,-17.857 7.761,-17.921 7.697,-17.965 7.62,-17.98 7.62,-17.98 7.543,-17.965 7.479,-17.921 7.435,-17.857 7.42,-17.78 7.42,-17.78 7.435,-17.703 7.479,-17.639 7.543,-17.595 7.62,-17.58 7.62,-17.58 7.697,-17.595 7.761,-17.639 7.805,-17.703 7.82,-17.78
  Top Layer-L1 keep-out region: 6.55,-17.78 6.535,-17.857 6.491,-17.921 6.427,-17.965 6.35,-17.98 6.35,-17.98 6.273,-17.965 6.209,-17.921 6.165,-17.857 6.15,-17.78 6.15,-17.78 6.165,-17.703 6.209,-17.639 6.273,-17.595 6.35,-17.58 6.35,-17.58 6.427,-17.595 6.491,-17.639 6.535,-17.703 6.55,-17.78
  Top Layer-L1 keep-out region: 5.28,-17.78 5.265,-17.857 5.221,-17.921 5.157,-17.965 5.08,-17.98 5.08,-17.98 5.003,-17.965 4.939,-17.921 4.895,-17.857 4.88,-17.78 4.88,-17.78 4.895,-17.703 4.939,-17.639 5.003,-17.595 5.08,-17.58 5.08,-17.58 5.157,-17.595 5.221,-17.639 5.265,-17.703 5.28,-17.78
  Top Layer-L1 keep-out region: 4.01,-17.78 3.995,-17.857 3.951,-17.921 3.887,-17.965 3.81,-17.98 3.81,-17.98 3.733,-17.965 3.669,-17.921 3.625,-17.857 3.61,-17.78 3.61,-17.78 3.625,-17.703 3.669,-17.639 3.733,-17.595 3.81,-17.58 3.81,-17.58 3.887,-17.595 3.951,-17.639 3.995,-17.703 4.01,-17.78
  Top Layer-L1 keep-out region: 2.74,-17.78 2.725,-17.857 2.681,-17.921 2.617,-17.965 2.54,-17.98 2.54,-17.98 2.463,-17.965 2.399,-17.921 2.355,-17.857 2.34,-17.78 2.34,-17.78 2.355,-17.703 2.399,-17.639 2.463,-17.595 2.54,-17.58 2.54,-17.58 2.617,-17.595 2.681,-17.639 2.725,-17.703 2.74,-17.78
  Top Layer-L1 keep-out region: 1.47,-17.78 1.455,-17.857 1.411,-17.921 1.347,-17.965 1.27,-17.98 1.27,-17.98 1.193,-17.965 1.129,-17.921 1.085,-17.857 1.07,-17.78 1.07,-17.78 1.085,-17.703 1.129,-17.639 1.193,-17.595 1.27,-17.58 1.27,-17.58 1.347,-17.595 1.411,-17.639 1.455,-17.703 1.47,-17.78
  Top Layer-L1 keep-out region: 0.2,-17.78 0.185,-17.857 0.141,-17.921 0.077,-17.965 0,-17.98 0,-17.98 -0.077,-17.965 -0.141,-17.921 -0.185,-17.857 -0.2,-17.78 -0.2,-17.78 -0.185,-17.703 -0.141,-17.639 -0.077,-17.595 0,-17.58 0,-17.58 0.077,-17.595 0.141,-17.639 0.185,-17.703 0.2,-17.78
  Top Layer-L1 keep-out region: -1.07,-17.78 -1.085,-17.857 -1.129,-17.921 -1.193,-17.965 -1.27,-17.98 -1.27,-17.98 -1.347,-17.965 -1.411,-17.921 -1.455,-17.857 -1.47,-17.78 -1.47,-17.78 -1.455,-17.703 -1.411,-17.639 -1.347,-17.595 -1.27,-17.58 -1.27,-17.58 -1.193,-17.595 -1.129,-17.639 -1.085,-17.703 -1.07,-17.78
  Top Layer-L1 keep-out region: -2.34,-17.78 -2.355,-17.857 -2.399,-17.921 -2.463,-17.965 -2.54,-17.98 -2.54,-17.98 -2.617,-17.965 -2.681,-17.921 -2.725,-17.857 -2.74,-17.78 -2.74,-17.78 -2.725,-17.703 -2.681,-17.639 -2.617,-17.595 -2.54,-17.58 -2.54,-17.58 -2.463,-17.595 -2.399,-17.639 -2.355,-17.703 -2.34,-17.78
  Top Layer-L1 keep-out region: -3.61,-17.78 -3.625,-17.857 -3.669,-17.921 -3.733,-17.965 -3.81,-17.98 -3.81,-17.98 -3.887,-17.965 -3.951,-17.921 -3.995,-17.857 -4.01,-17.78 -4.01,-17.78 -3.995,-17.703 -3.951,-17.639 -3.887,-17.595 -3.81,-17.58 -3.81,-17.58 -3.733,-17.595 -3.669,-17.639 -3.625,-17.703 -3.61,-17.78
  Top Layer-L1 keep-out region: -4.88,-17.78 -4.895,-17.857 -4.939,-17.921 -5.003,-17.965 -5.08,-17.98 -5.08,-17.98 -5.157,-17.965 -5.221,-17.921 -5.265,-17.857 -5.28,-17.78 -5.28,-17.78 -5.265,-17.703 -5.221,-17.639 -5.157,-17.595 -5.08,-17.58 -5.08,-17.58 -5.003,-17.595 -4.939,-17.639 -4.895,-17.703 -4.88,-17.78
  Top Layer-L1 keep-out region: -6.15,-17.78 -6.165,-17.857 -6.209,-17.921 -6.273,-17.965 -6.35,-17.98 -6.35,-17.98 -6.427,-17.965 -6.491,-17.921 -6.535,-17.857 -6.55,-17.78 -6.55,-17.78 -6.535,-17.703 -6.491,-17.639 -6.427,-17.595 -6.35,-17.58 -6.35,-17.58 -6.273,-17.595 -6.209,-17.639 -6.165,-17.703 -6.15,-17.78
  Top Layer-L1 keep-out region: -7.42,-17.78 -7.435,-17.857 -7.479,-17.921 -7.543,-17.965 -7.62,-17.98 -7.62,-17.98 -7.697,-17.965 -7.761,-17.921 -7.805,-17.857 -7.82,-17.78 -7.82,-17.78 -7.805,-17.703 -7.761,-17.639 -7.697,-17.595 -7.62,-17.58 -7.62,-17.58 -7.543,-17.595 -7.479,-17.639 -7.435,-17.703 -7.42,-17.78
  Top Layer-L1 keep-out region: -8.69,-17.78 -8.705,-17.857 -8.749,-17.921 -8.813,-17.965 -8.89,-17.98 -8.89,-17.98 -8.967,-17.965 -9.031,-17.921 -9.075,-17.857 -9.09,-17.78 -9.09,-17.78 -9.075,-17.703 -9.031,-17.639 -8.967,-17.595 -8.89,-17.58 -8.89,-17.58 -8.813,-17.595 -8.749,-17.639 -8.705,-17.703 -8.69,-17.78
  Top Layer-L1 keep-out region: -9.96,-17.78 -9.975,-17.857 -10.019,-17.921 -10.083,-17.965 -10.16,-17.98 -10.16,-17.98 -10.237,-17.965 -10.301,-17.921 -10.345,-17.857 -10.36,-17.78 -10.36,-17.78 -10.345,-17.703 -10.301,-17.639 -10.237,-17.595 -10.16,-17.58 -10.16,-17.58 -10.083,-17.595 -10.019,-17.639 -9.975,-17.703 -9.96,-17.78
  Top Layer-L1 keep-out region: -11.23,-17.78 -11.245,-17.857 -11.289,-17.921 -11.353,-17.965 -11.43,-17.98 -11.43,-17.98 -11.507,-17.965 -11.571,-17.921 -11.615,-17.857 -11.63,-17.78 -11.63,-17.78 -11.615,-17.703 -11.571,-17.639 -11.507,-17.595 -11.43,-17.58 -11.43,-17.58 -11.353,-17.595 -11.289,-17.639 -11.245,-17.703 -11.23,-17.78
  Top Layer-L1 keep-out region: -12.5,-17.78 -12.515,-17.857 -12.559,-17.921 -12.623,-17.965 -12.7,-17.98 -12.7,-17.98 -12.777,-17.965 -12.841,-17.921 -12.885,-17.857 -12.9,-17.78 -12.9,-17.78 -12.885,-17.703 -12.841,-17.639 -12.777,-17.595 -12.7,-17.58 -12.7,-17.58 -12.623,-17.595 -12.559,-17.639 -12.515,-17.703 -12.5,-17.78
  Top Layer-L1 keep-out region: -13.77,-17.78 -13.785,-17.857 -13.829,-17.921 -13.893,-17.965 -13.97,-17.98 -13.97,-17.98 -14.047,-17.965 -14.111,-17.921 -14.155,-17.857 -14.17,-17.78 -14.17,-17.78 -14.155,-17.703 -14.111,-17.639 -14.047,-17.595 -13.97,-17.58 -13.97,-17.58 -13.893,-17.595 -13.829,-17.639 -13.785,-17.703 -13.77,-17.78
  Top Layer-L1 keep-out region: -15.04,-17.78 -15.055,-17.857 -15.099,-17.921 -15.163,-17.965 -15.24,-17.98 -15.24,-17.98 -15.317,-17.965 -15.381,-17.921 -15.425,-17.857 -15.44,-17.78 -15.44,-17.78 -15.425,-17.703 -15.381,-17.639 -15.317,-17.595 -15.24,-17.58 -15.24,-17.58 -15.163,-17.595 -15.099,-17.639 -15.055,-17.703 -15.04,-17.78
  Top Layer-L1 keep-out region: -16.31,-17.78 -16.325,-17.857 -16.369,-17.921 -16.433,-17.965 -16.51,-17.98 -16.51,-17.98 -16.587,-17.965 -16.651,-17.921 -16.695,-17.857 -16.71,-17.78 -16.71,-17.78 -16.695,-17.703 -16.651,-17.639 -16.587,-17.595 -16.51,-17.58 -16.51,-17.58 -16.433,-17.595 -16.369,-17.639 -16.325,-17.703 -16.31,-17.78
  Top Layer-L1 keep-out region: 17.98,-16.51 17.965,-16.587 17.921,-16.651 17.857,-16.695 17.78,-16.71 17.78,-16.71 17.703,-16.695 17.639,-16.651 17.595,-16.587 17.58,-16.51 17.58,-16.51 17.595,-16.433 17.639,-16.369 17.703,-16.325 17.78,-16.31 17.78,-16.31 17.857,-16.325 17.921,-16.369 17.965,-16.433 17.98,-16.51
  Top Layer-L1 keep-out region: 16.71,-16.51 16.695,-16.587 16.651,-16.651 16.587,-16.695 16.51,-16.71 16.51,-16.71 16.433,-16.695 16.369,-16.651 16.325,-16.587 16.31,-16.51 16.31,-16.51 16.325,-16.433 16.369,-16.369 16.433,-16.325 16.51,-16.31 16.51,-16.31 16.587,-16.325 16.651,-16.369 16.695,-16.433 16.71,-16.51
  Top Layer-L1 keep-out region: 15.44,-16.51 15.425,-16.587 15.381,-16.651 15.317,-16.695 15.24,-16.71 15.24,-16.71 15.163,-16.695 15.099,-16.651 15.055,-16.587 15.04,-16.51 15.04,-16.51 15.055,-16.433 15.099,-16.369 15.163,-16.325 15.24,-16.31 15.24,-16.31 15.317,-16.325 15.381,-16.369 15.425,-16.433 15.44,-16.51
  Top Layer-L1 keep-out region: 14.17,-16.51 14.155,-16.587 14.111,-16.651 14.047,-16.695 13.97,-16.71 13.97,-16.71 13.893,-16.695 13.829,-16.651 13.785,-16.587 13.77,-16.51 13.77,-16.51 13.785,-16.433 13.829,-16.369 13.893,-16.325 13.97,-16.31 13.97,-16.31 14.047,-16.325 14.111,-16.369 14.155,-16.433 14.17,-16.51
  Top Layer-L1 keep-out region: 12.9,-16.51 12.885,-16.587 12.841,-16.651 12.777,-16.695 12.7,-16.71 12.7,-16.71 12.623,-16.695 12.559,-16.651 12.515,-16.587 12.5,-16.51 12.5,-16.51 12.515,-16.433 12.559,-16.369 12.623,-16.325 12.7,-16.31 12.7,-16.31 12.777,-16.325 12.841,-16.369 12.885,-16.433 12.9,-16.51
  Top Layer-L1 keep-out region: 11.63,-16.51 11.615,-16.587 11.571,-16.651 11.507,-16.695 11.43,-16.71 11.43,-16.71 11.353,-16.695 11.289,-16.651 11.245,-16.587 11.23,-16.51 11.23,-16.51 11.245,-16.433 11.289,-16.369 11.353,-16.325 11.43,-16.31 11.43,-16.31 11.507,-16.325 11.571,-16.369 11.615,-16.433 11.63,-16.51
  Top Layer-L1 keep-out region: 10.36,-16.51 10.345,-16.587 10.301,-16.651 10.237,-16.695 10.16,-16.71 10.16,-16.71 10.083,-16.695 10.019,-16.651 9.975,-16.587 9.96,-16.51 9.96,-16.51 9.975,-16.433 10.019,-16.369 10.083,-16.325 10.16,-16.31 10.16,-16.31 10.237,-16.325 10.301,-16.369 10.345,-16.433 10.36,-16.51
  Top Layer-L1 keep-out region: 9.09,-16.51 9.075,-16.587 9.031,-16.651 8.967,-16.695 8.89,-16.71 8.89,-16.71 8.813,-16.695 8.749,-16.651 8.705,-16.587 8.69,-16.51 8.69,-16.51 8.705,-16.433 8.749,-16.369 8.813,-16.325 8.89,-16.31 8.89,-16.31 8.967,-16.325 9.031,-16.369 9.075,-16.433 9.09,-16.51
  Top Layer-L1 keep-out region: 7.82,-16.51 7.805,-16.587 7.761,-16.651 7.697,-16.695 7.62,-16.71 7.62,-16.71 7.543,-16.695 7.479,-16.651 7.435,-16.587 7.42,-16.51 7.42,-16.51 7.435,-16.433 7.479,-16.369 7.543,-16.325 7.62,-16.31 7.62,-16.31 7.697,-16.325 7.761,-16.369 7.805,-16.433 7.82,-16.51
  Top Layer-L1 keep-out region: 6.55,-16.51 6.535,-16.587 6.491,-16.651 6.427,-16.695 6.35,-16.71 6.35,-16.71 6.273,-16.695 6.209,-16.651 6.165,-16.587 6.15,-16.51 6.15,-16.51 6.165,-16.433 6.209,-16.369 6.273,-16.325 6.35,-16.31 6.35,-16.31 6.427,-16.325 6.491,-16.369 6.535,-16.433 6.55,-16.51
  Top Layer-L1 keep-out region: 5.28,-16.51 5.265,-16.587 5.221,-16.651 5.157,-16.695 5.08,-16.71 5.08,-16.71 5.003,-16.695 4.939,-16.651 4.895,-16.587 4.88,-16.51 4.88,-16.51 4.895,-16.433 4.939,-16.369 5.003,-16.325 5.08,-16.31 5.08,-16.31 5.157,-16.325 5.221,-16.369 5.265,-16.433 5.28,-16.51
  Top Layer-L1 keep-out region: 4.01,-16.51 3.995,-16.587 3.951,-16.651 3.887,-16.695 3.81,-16.71 3.81,-16.71 3.733,-16.695 3.669,-16.651 3.625,-16.587 3.61,-16.51 3.61,-16.51 3.625,-16.433 3.669,-16.369 3.733,-16.325 3.81,-16.31 3.81,-16.31 3.887,-16.325 3.951,-16.369 3.995,-16.433 4.01,-16.51
  Top Layer-L1 keep-out region: 2.74,-16.51 2.725,-16.587 2.681,-16.651 2.617,-16.695 2.54,-16.71 2.54,-16.71 2.463,-16.695 2.399,-16.651 2.355,-16.587 2.34,-16.51 2.34,-16.51 2.355,-16.433 2.399,-16.369 2.463,-16.325 2.54,-16.31 2.54,-16.31 2.617,-16.325 2.681,-16.369 2.725,-16.433 2.74,-16.51
  Top Layer-L1 keep-out region: 1.47,-16.51 1.455,-16.587 1.411,-16.651 1.347,-16.695 1.27,-16.71 1.27,-16.71 1.193,-16.695 1.129,-16.651 1.085,-16.587 1.07,-16.51 1.07,-16.51 1.085,-16.433 1.129,-16.369 1.193,-16.325 1.27,-16.31 1.27,-16.31 1.347,-16.325 1.411,-16.369 1.455,-16.433 1.47,-16.51
  Top Layer-L1 keep-out region: 0.2,-16.51 0.185,-16.587 0.141,-16.651 0.077,-16.695 0,-16.71 0,-16.71 -0.077,-16.695 -0.141,-16.651 -0.185,-16.587 -0.2,-16.51 -0.2,-16.51 -0.185,-16.433 -0.141,-16.369 -0.077,-16.325 0,-16.31 0,-16.31 0.077,-16.325 0.141,-16.369 0.185,-16.433 0.2,-16.51
  Top Layer-L1 keep-out region: -1.07,-16.51 -1.085,-16.587 -1.129,-16.651 -1.193,-16.695 -1.27,-16.71 -1.27,-16.71 -1.347,-16.695 -1.411,-16.651 -1.455,-16.587 -1.47,-16.51 -1.47,-16.51 -1.455,-16.433 -1.411,-16.369 -1.347,-16.325 -1.27,-16.31 -1.27,-16.31 -1.193,-16.325 -1.129,-16.369 -1.085,-16.433 -1.07,-16.51
  Top Layer-L1 keep-out region: -2.34,-16.51 -2.355,-16.587 -2.399,-16.651 -2.463,-16.695 -2.54,-16.71 -2.54,-16.71 -2.617,-16.695 -2.681,-16.651 -2.725,-16.587 -2.74,-16.51 -2.74,-16.51 -2.725,-16.433 -2.681,-16.369 -2.617,-16.325 -2.54,-16.31 -2.54,-16.31 -2.463,-16.325 -2.399,-16.369 -2.355,-16.433 -2.34,-16.51
  Top Layer-L1 keep-out region: -3.61,-16.51 -3.625,-16.587 -3.669,-16.651 -3.733,-16.695 -3.81,-16.71 -3.81,-16.71 -3.887,-16.695 -3.951,-16.651 -3.995,-16.587 -4.01,-16.51 -4.01,-16.51 -3.995,-16.433 -3.951,-16.369 -3.887,-16.325 -3.81,-16.31 -3.81,-16.31 -3.733,-16.325 -3.669,-16.369 -3.625,-16.433 -3.61,-16.51
  Top Layer-L1 keep-out region: -4.88,-16.51 -4.895,-16.587 -4.939,-16.651 -5.003,-16.695 -5.08,-16.71 -5.08,-16.71 -5.157,-16.695 -5.221,-16.651 -5.265,-16.587 -5.28,-16.51 -5.28,-16.51 -5.265,-16.433 -5.221,-16.369 -5.157,-16.325 -5.08,-16.31 -5.08,-16.31 -5.003,-16.325 -4.939,-16.369 -4.895,-16.433 -4.88,-16.51
  Top Layer-L1 keep-out region: -6.15,-16.51 -6.165,-16.587 -6.209,-16.651 -6.273,-16.695 -6.35,-16.71 -6.35,-16.71 -6.427,-16.695 -6.491,-16.651 -6.535,-16.587 -6.55,-16.51 -6.55,-16.51 -6.535,-16.433 -6.491,-16.369 -6.427,-16.325 -6.35,-16.31 -6.35,-16.31 -6.273,-16.325 -6.209,-16.369 -6.165,-16.433 -6.15,-16.51
  Top Layer-L1 keep-out region: -7.42,-16.51 -7.435,-16.587 -7.479,-16.651 -7.543,-16.695 -7.62,-16.71 -7.62,-16.71 -7.697,-16.695 -7.761,-16.651 -7.805,-16.587 -7.82,-16.51 -7.82,-16.51 -7.805,-16.433 -7.761,-16.369 -7.697,-16.325 -7.62,-16.31 -7.62,-16.31 -7.543,-16.325 -7.479,-16.369 -7.435,-16.433 -7.42,-16.51
  Top Layer-L1 keep-out region: -8.69,-16.51 -8.705,-16.587 -8.749,-16.651 -8.813,-16.695 -8.89,-16.71 -8.89,-16.71 -8.967,-16.695 -9.031,-16.651 -9.075,-16.587 -9.09,-16.51 -9.09,-16.51 -9.075,-16.433 -9.031,-16.369 -8.967,-16.325 -8.89,-16.31 -8.89,-16.31 -8.813,-16.325 -8.749,-16.369 -8.705,-16.433 -8.69,-16.51
  Top Layer-L1 keep-out region: -9.96,-16.51 -9.975,-16.587 -10.019,-16.651 -10.083,-16.695 -10.16,-16.71 -10.16,-16.71 -10.237,-16.695 -10.301,-16.651 -10.345,-16.587 -10.36,-16.51 -10.36,-16.51 -10.345,-16.433 -10.301,-16.369 -10.237,-16.325 -10.16,-16.31 -10.16,-16.31 -10.083,-16.325 -10.019,-16.369 -9.975,-16.433 -9.96,-16.51
  Top Layer-L1 keep-out region: -11.23,-16.51 -11.245,-16.587 -11.289,-16.651 -11.353,-16.695 -11.43,-16.71 -11.43,-16.71 -11.507,-16.695 -11.571,-16.651 -11.615,-16.587 -11.63,-16.51 -11.63,-16.51 -11.615,-16.433 -11.571,-16.369 -11.507,-16.325 -11.43,-16.31 -11.43,-16.31 -11.353,-16.325 -11.289,-16.369 -11.245,-16.433 -11.23,-16.51
  Top Layer-L1 keep-out region: -12.5,-16.51 -12.515,-16.587 -12.559,-16.651 -12.623,-16.695 -12.7,-16.71 -12.7,-16.71 -12.777,-16.695 -12.841,-16.651 -12.885,-16.587 -12.9,-16.51 -12.9,-16.51 -12.885,-16.433 -12.841,-16.369 -12.777,-16.325 -12.7,-16.31 -12.7,-16.31 -12.623,-16.325 -12.559,-16.369 -12.515,-16.433 -12.5,-16.51
  Top Layer-L1 keep-out region: -13.77,-16.51 -13.785,-16.587 -13.829,-16.651 -13.893,-16.695 -13.97,-16.71 -13.97,-16.71 -14.047,-16.695 -14.111,-16.651 -14.155,-16.587 -14.17,-16.51 -14.17,-16.51 -14.155,-16.433 -14.111,-16.369 -14.047,-16.325 -13.97,-16.31 -13.97,-16.31 -13.893,-16.325 -13.829,-16.369 -13.785,-16.433 -13.77,-16.51
  Top Layer-L1 keep-out region: -15.04,-16.51 -15.055,-16.587 -15.099,-16.651 -15.163,-16.695 -15.24,-16.71 -15.24,-16.71 -15.317,-16.695 -15.381,-16.651 -15.425,-16.587 -15.44,-16.51 -15.44,-16.51 -15.425,-16.433 -15.381,-16.369 -15.317,-16.325 -15.24,-16.31 -15.24,-16.31 -15.163,-16.325 -15.099,-16.369 -15.055,-16.433 -15.04,-16.51
  Top Layer-L1 keep-out region: -16.31,-16.51 -16.325,-16.587 -16.369,-16.651 -16.433,-16.695 -16.51,-16.71 -16.51,-16.71 -16.587,-16.695 -16.651,-16.651 -16.695,-16.587 -16.71,-16.51 -16.71,-16.51 -16.695,-16.433 -16.651,-16.369 -16.587,-16.325 -16.51,-16.31 -16.51,-16.31 -16.433,-16.325 -16.369,-16.369 -16.325,-16.433 -16.31,-16.51
  Top Layer-L1 keep-out region: -17.58,-16.51 -17.595,-16.587 -17.639,-16.651 -17.703,-16.695 -17.78,-16.71 -17.78,-16.71 -17.857,-16.695 -17.921,-16.651 -17.965,-16.587 -17.98,-16.51 -17.98,-16.51 -17.965,-16.433 -17.921,-16.369 -17.857,-16.325 -17.78,-16.31 -17.78,-16.31 -17.703,-16.325 -17.639,-16.369 -17.595,-16.433 -17.58,-16.51
  Top Layer-L1 keep-out region: 17.98,-15.24 17.965,-15.317 17.921,-15.381 17.857,-15.425 17.78,-15.44 17.78,-15.44 17.703,-15.425 17.639,-15.381 17.595,-15.317 17.58,-15.24 17.58,-15.24 17.595,-15.163 17.639,-15.099 17.703,-15.055 17.78,-15.04 17.78,-15.04 17.857,-15.055 17.921,-15.099 17.965,-15.163 17.98,-15.24
  Top Layer-L1 keep-out region: 16.71,-15.24 16.695,-15.317 16.651,-15.381 16.587,-15.425 16.51,-15.44 16.51,-15.44 16.433,-15.425 16.369,-15.381 16.325,-15.317 16.31,-15.24 16.31,-15.24 16.325,-15.163 16.369,-15.099 16.433,-15.055 16.51,-15.04 16.51,-15.04 16.587,-15.055 16.651,-15.099 16.695,-15.163 16.71,-15.24
  Top Layer-L1 keep-out region: 15.44,-15.24 15.425,-15.317 15.381,-15.381 15.317,-15.425 15.24,-15.44 15.24,-15.44 15.163,-15.425 15.099,-15.381 15.055,-15.317 15.04,-15.24 15.04,-15.24 15.055,-15.163 15.099,-15.099 15.163,-15.055 15.24,-15.04 15.24,-15.04 15.317,-15.055 15.381,-15.099 15.425,-15.163 15.44,-15.24
  Top Layer-L1 keep-out region: 14.17,-15.24 14.155,-15.317 14.111,-15.381 14.047,-15.425 13.97,-15.44 13.97,-15.44 13.893,-15.425 13.829,-15.381 13.785,-15.317 13.77,-15.24 13.77,-15.24 13.785,-15.163 13.829,-15.099 13.893,-15.055 13.97,-15.04 13.97,-15.04 14.047,-15.055 14.111,-15.099 14.155,-15.163 14.17,-15.24
  Top Layer-L1 keep-out region: 12.9,-15.24 12.885,-15.317 12.841,-15.381 12.777,-15.425 12.7,-15.44 12.7,-15.44 12.623,-15.425 12.559,-15.381 12.515,-15.317 12.5,-15.24 12.5,-15.24 12.515,-15.163 12.559,-15.099 12.623,-15.055 12.7,-15.04 12.7,-15.04 12.777,-15.055 12.841,-15.099 12.885,-15.163 12.9,-15.24
  Top Layer-L1 keep-out region: 11.63,-15.24 11.615,-15.317 11.571,-15.381 11.507,-15.425 11.43,-15.44 11.43,-15.44 11.353,-15.425 11.289,-15.381 11.245,-15.317 11.23,-15.24 11.23,-15.24 11.245,-15.163 11.289,-15.099 11.353,-15.055 11.43,-15.04 11.43,-15.04 11.507,-15.055 11.571,-15.099 11.615,-15.163 11.63,-15.24
  Top Layer-L1 keep-out region: 10.36,-15.24 10.345,-15.317 10.301,-15.381 10.237,-15.425 10.16,-15.44 10.16,-15.44 10.083,-15.425 10.019,-15.381 9.975,-15.317 9.96,-15.24 9.96,-15.24 9.975,-15.163 10.019,-15.099 10.083,-15.055 10.16,-15.04 10.16,-15.04 10.237,-15.055 10.301,-15.099 10.345,-15.163 10.36,-15.24
  Top Layer-L1 keep-out region: 9.09,-15.24 9.075,-15.317 9.031,-15.381 8.967,-15.425 8.89,-15.44 8.89,-15.44 8.813,-15.425 8.749,-15.381 8.705,-15.317 8.69,-15.24 8.69,-15.24 8.705,-15.163 8.749,-15.099 8.813,-15.055 8.89,-15.04 8.89,-15.04 8.967,-15.055 9.031,-15.099 9.075,-15.163 9.09,-15.24
  Top Layer-L1 keep-out region: 7.82,-15.24 7.805,-15.317 7.761,-15.381 7.697,-15.425 7.62,-15.44 7.62,-15.44 7.543,-15.425 7.479,-15.381 7.435,-15.317 7.42,-15.24 7.42,-15.24 7.435,-15.163 7.479,-15.099 7.543,-15.055 7.62,-15.04 7.62,-15.04 7.697,-15.055 7.761,-15.099 7.805,-15.163 7.82,-15.24
  Top Layer-L1 keep-out region: 6.55,-15.24 6.535,-15.317 6.491,-15.381 6.427,-15.425 6.35,-15.44 6.35,-15.44 6.273,-15.425 6.209,-15.381 6.165,-15.317 6.15,-15.24 6.15,-15.24 6.165,-15.163 6.209,-15.099 6.273,-15.055 6.35,-15.04 6.35,-15.04 6.427,-15.055 6.491,-15.099 6.535,-15.163 6.55,-15.24
  Top Layer-L1 keep-out region: 5.28,-15.24 5.265,-15.317 5.221,-15.381 5.157,-15.425 5.08,-15.44 5.08,-15.44 5.003,-15.425 4.939,-15.381 4.895,-15.317 4.88,-15.24 4.88,-15.24 4.895,-15.163 4.939,-15.099 5.003,-15.055 5.08,-15.04 5.08,-15.04 5.157,-15.055 5.221,-15.099 5.265,-15.163 5.28,-15.24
